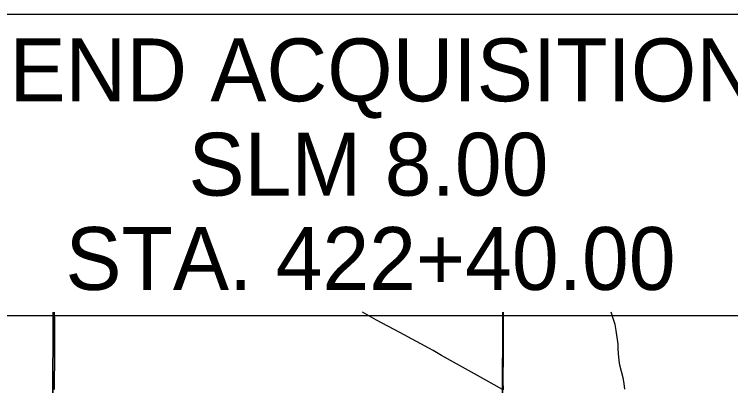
# Model space of a CAD drawing. Extents: x 0 to 34, y 0 to 22.
# Drawn here: x 3.355 to 4.949, y 18.817 to 19.644 of the extents above; entities that cross this region are included whole.
import ezdxf

# ---------------------------------------------------------------- set-up
doc = ezdxf.new("R2010")
doc.units = 0
for name, color, linetype in [('GM_X_County_Road', 7, 'Continuous'), ('GM_X_Minor_River', 7, 'Continuous'), ('GM_X_Section', 7, 'Continuous'), ('GM_X_State_Route', 7, 'Continuous'), ('GM_X_Township_Road', 7, 'Continuous'), ('SH_Text', 7, 'Continuous')]:
    doc.layers.add(name, color=color, linetype=linetype)

msp = doc.modelspace()

# ---------------------------------------------------------------- linework, layer by layer
at = {"layer": 'GM_X_County_Road'}
for p, q in [((3.4445, 18.9603), (3.4444, 18.9805)), ((3.4447, 18.8904), (3.4445, 18.9603)), ((3.4444, 18.8085), (3.4447, 18.8904))]:
    msp.add_line(p, q, dxfattribs=at)
at = {"layer": 'GM_X_Minor_River'}
for p, q in [((4.6838, 18.978), (4.683, 18.9805)), ((4.6879, 18.9666), (4.6838, 18.978)), ((4.692, 18.9529), (4.6879, 18.9666)), ((4.6946, 18.9396), (4.692, 18.9529)), ((4.6961, 18.9293), (4.6946, 18.9396)), ((4.6972, 18.9195), (4.6961, 18.9293)), ((4.6987, 18.9096), (4.6972, 18.9195)), ((4.699, 18.8993), (4.6987, 18.9096)), ((4.6997, 18.8883), (4.699, 18.8993)), ((4.7008, 18.8731), (4.6997, 18.8883)), ((4.7026, 18.8629), (4.7008, 18.8731)), ((4.7067, 18.8484), (4.7026, 18.8629)), ((4.7104, 18.834), (4.7067, 18.8484)), ((4.7123, 18.8218), (4.7104, 18.834)), ((4.7141, 18.8093), (4.7123, 18.8218))]:
    msp.add_line(p, q, dxfattribs=at)
at = {"layer": 'GM_X_Section'}
for p, q in [((3.4389, 18.3043), (3.4412, 18.9805)), ((3.4412, 18.9805), (3.4389, 18.3043)), ((4.4424, 18.9805), (4.4382, 18.3016)), ((4.4382, 18.3016), (4.4424, 18.9805))]:
    msp.add_line(p, q, dxfattribs=at)
at = {"layer": 'GM_X_State_Route'}
for p, q in [((4.1611, 18.9629), (4.1294, 18.9805)), ((4.2132, 18.9351), (4.1611, 18.9629)), ((4.2869, 18.895), (4.2132, 18.9351)), ((4.3058, 18.8844), (4.2869, 18.895)), ((4.3788, 18.843), (4.3058, 18.8844)), ((4.4413, 18.8083), (4.3788, 18.843))]:
    msp.add_line(p, q, dxfattribs=at)
at = {"layer": 'GM_X_Township_Road'}
for p, q in [((4.4434, 18.932), (4.4438, 18.9805)), ((4.4434, 18.8885), (4.4434, 18.932)), ((4.443, 18.8264), (4.4434, 18.8885)), ((4.4433, 18.8073), (4.443, 18.8264))]:
    msp.add_line(p, q, dxfattribs=at)
at = {"layer": 'SH_Text'}
msp.add_lwpolyline([(3.304, 19.6439), (5.0268, 19.6439), (5.0268, 18.9722), (3.304, 18.9722)], close=True, dxfattribs=at)

# ---------------------------------------------------------------- texts
for s, p in [('END ACQUISITION', (3.3438, 19.4501)), ('SLM 8.00', (3.7423, 19.2401)), ('STA. 422+40.00', (3.4684, 19.0301))]:
    msp.add_text(s, height=0.14, dxfattribs=at).set_placement(p)

doc.saveas('drawing.dxf')
